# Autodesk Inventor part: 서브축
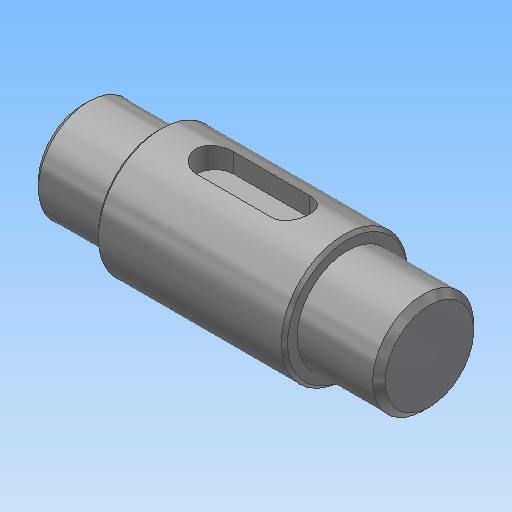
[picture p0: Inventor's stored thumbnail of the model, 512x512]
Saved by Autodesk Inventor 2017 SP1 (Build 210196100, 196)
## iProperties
Created: 2019-03
Part Number: 서브축
Material: 강철, 연강
Document SubType Name: Modeling
Designer: mduedu
Density: 1 g/cm^3
Appearance: 강철
Author: mduedu
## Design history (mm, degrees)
sketch "스케치1"
  geometry: L1 (0, 0)-(12, 0); L2 (12, 0)-(12, 8); L3 (12, 8)-(0, 8); L4 (0, 8)-(0, 0); L5 (12, 0)-(42, 0); L6 (42, 0)-(42, 10); L7 (42, 10)-(12, 10); L8 (12, 10)-(12, 0); L9 (42, 0)-(55, 0); L10 (55, 0)-(55, 8); L11 (55, 8)-(42, 8); L12 (42, 8)-(42, 0)
  constraints: 24 end point, 6 parallel, 3 horizontal, 3 perpendicular
  dimensions: "d0" = 16 diameter of L3 L1; "d2" = 20 diameter of L7 L5; "d3" = 16 diameter of L11 L9; "d4" = 12 distance of L2.end L3.end; "d5" = 30 distance of L6.end L7.end; "d6" = 55 distance between parallel lines of L10 L4
revolve "회전1" sketch "스케치1" stored, may be unused: angle "d7" = 90 deg
node "작업 평면1"
sketch "스케치2" dims "d10" = 18
  geometry: L1 (6, -3)-(-6, -3); L2 (-6, -3)-(-6, 3); L3 (-6, 3)-(6, 3); L4 (6, 3)-(6, -3); L5 (15, 10)-(15, -10) reference; 3 further points
  constraints: 8 end point, 2 midpoint, 2 parallel, 2 vertical alignment, 1 horizontal, 1 horizontal alignment, 1 perpendicular, 4 other
  dimensions: "d8" = 6 distance between parallel lines of L3 L1; "d11" = 6 dimension on L5
extrude "돌출1" cut sketch "스케치2" distance "d12" = 3.5; taper "d13" = 0 deg
chamfer "모따기1" distance "d14" = 1; stored, may be unused: second distance "d15" = 2, angle "d16" = 45 deg
chamfer "모따기2" distance "d17" = 0.5; stored, may be unused: second distance "d18" = 2, angle "d19" = 45 deg
node "솔리드1"
